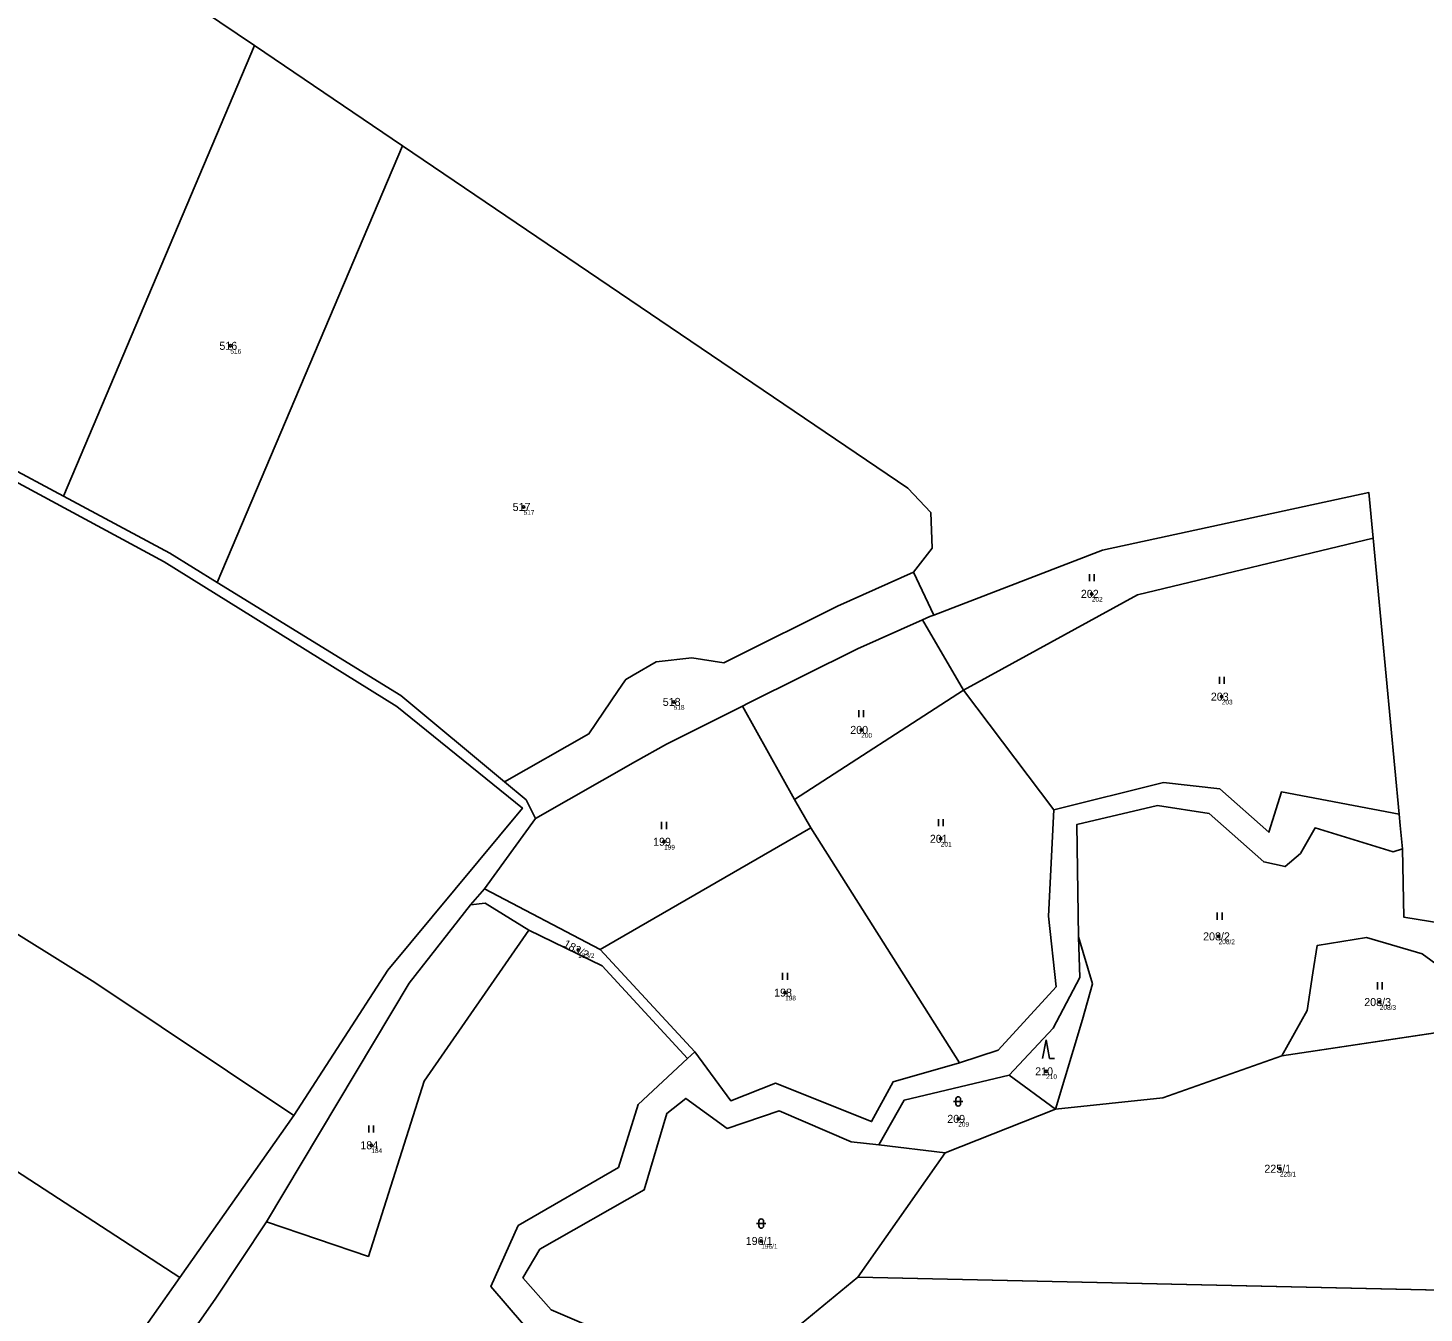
# Model space of a CAD drawing. Extents: x -700238 to -698499, y -1070626 to -1068006.
# Drawn here: x -699496.9 to -699200.2, y -1068765.8 to -1068492.8 of the extents above; entities that cross this region are included whole.
import ezdxf

# ---------------------------------------------------------------- set-up
doc = ezdxf.new("R2010")
doc.units = 0
for name, color, linetype in [('Definiční body', 7, 'Continuous'), ('Hranice parcel', 7, 'Continuous'), ('Parcelní čísla', 7, 'Continuous'), ('Polygon ku', 7, 'Continuous'), ('Polygon parcely', 7, 'Continuous'), ('Značky kultur', 7, 'Continuous')]:
    doc.layers.add(name, color=color, linetype=linetype)

msp = doc.modelspace()

# ---------------------------------------------------------------- linework, layer by layer
at = {"layer": 'Definiční body'}
for centre in [(-699453.85, -1068560.32994), (-699391.54, -1068594.54994), (-699270.81, -1068613.00994), (-699359.65, -1068635.95994), (-699243.2, -1068634.84994), (-699319.81, -1068641.90994), (-699361.7, -1068665.66994), (-699302.9, -1068665.03994), (-699243.87, -1068685.76994), (-699379.94, -1068688.68994), (-699335.99, -1068697.70994), (-699209.63, -1068699.71994), (-699280.52, -1068714.42994), (-699299.2, -1068724.52994), (-699423.9, -1068730.13994), (-699230.86, -1068735.11994), (-699341.05, -1068750.45994)]:
    msp.add_circle(centre, 0.25, dxfattribs=at)
at = {"layer": 'Hranice parcel'}
for p, q in [((-699459.74, -1068489.07), (-699448.71, -1068496.54)), ((-699489.31, -1068592.29), (-699448.71, -1068496.54)), ((-699448.71, -1068496.54), (-699417.3, -1068517.82)), ((-699456.64, -1068610.59), (-699417.3, -1068517.82)), ((-699211.93, -1068591.51), (-699211.02, -1068601.19)), ((-699211.02, -1068601.19), (-699205.5, -1068659.82)), ((-699308.68, -1068608.43), (-699304.4, -1068617.51)), ((-699305.24, -1068617.83), (-699306.78, -1068618.51)), ((-699304.4, -1068617.51), (-699305.24, -1068617.83)), ((-699306.78, -1068618.51), (-699320.61, -1068624.67)), ((-699298.09, -1068633.47), (-699306.78, -1068618.51)), ((-699334.01, -1068656.7), (-699298.09, -1068633.47)), ((-699298.09, -1068633.47), (-699278.9, -1068658.92)), ((-699345.02, -1068636.87), (-699334.01, -1068656.7)), ((-699330.48, -1068662.71), (-699334.01, -1068656.7)), ((-699205.5, -1068659.82), (-699205.28, -1068662.2)), ((-699399.84, -1068675.68), (-699389.04, -1068660.7)), ((-699330.48, -1068662.71), (-699375.27, -1068688.59)), ((-699298.89, -1068712.63), (-699330.48, -1068662.71)), ((-699205.28, -1068662.2), (-699204.82, -1068667.14)), ((-699402.82, -1068679.09), (-699399.84, -1068675.68)), ((-699375.27, -1068688.59), (-699399.84, -1068675.68)), ((-699355.18, -1068710.3), (-699375.27, -1068688.59)), ((-699176.6, -1068703.08), (-699230.46, -1068711.14)), ((-699355.18, -1068710.3), (-699356.75, -1068711.69)), ((-699278.5, -1068722.49), (-699288.39, -1068715.22)), ((-699440.37, -1068723.79), (-699464.55, -1068758.22)), ((-699302, -1068731.73), (-699278.5, -1068722.49)), ((-699302, -1068731.73), (-699316.06, -1068730.07)), ((-699320.54, -1068758.12), (-699302, -1068731.73)), ((-699320.54, -1068758.12), (-699164.78, -1068761.6))]:
    msp.add_line(p, q, dxfattribs=at)
for points in [[(-699417.3, -1068517.82), (-699309.92, -1068590.54), (-699305.03, -1068595.73), (-699304.73, -1068603.32), (-699308.68, -1068608.43)], [(-699489.31, -1068592.29), (-699514.72, -1068578.68), (-699545.8, -1068564.77), (-699583.54, -1068551.89)], [(-699584.32, -1068553.61), (-699551.31, -1068565.08), (-699541.03, -1068568.61), (-699514.77, -1068580.92), (-699467.93, -1068606.23), (-699418.44, -1068636.97), (-699391.79, -1068658.5), (-699420.37, -1068692.98), (-699440.37, -1068723.79)], [(-699211.93, -1068591.51), (-699268.51, -1068603.73), (-699304.4, -1068617.51)], [(-699456.64, -1068610.59), (-699466.71, -1068604.39), (-699489.31, -1068592.29)], [(-699211.02, -1068601.19), (-699261.08, -1068613.24), (-699298.09, -1068633.47)], [(-699440.37, -1068723.79), (-699482.65, -1068695.57), (-699529.3, -1068666.47), (-699581.06, -1068637.52), (-699612.14, -1068624.01), (-699666.08, -1068607.69)], [(-699395.63, -1068652.94), (-699377.65, -1068642.77), (-699371.43, -1068633.55), (-699370.04, -1068631.49), (-699369.83, -1068631.17), (-699368.26, -1068630.27), (-699363.39, -1068627.48), (-699355.83, -1068626.57), (-699349.02, -1068627.65), (-699347.33, -1068626.81), (-699324.87, -1068615.62), (-699308.68, -1068608.43)], [(-699395.63, -1068652.94), (-699417.63, -1068634.59), (-699456.64, -1068610.59)], [(-699320.61, -1068624.67), (-699343.8, -1068636.26), (-699345.02, -1068636.87)], [(-699345.02, -1068636.87), (-699361.16, -1068644.93), (-699367.73, -1068648.65), (-699389.04, -1068660.7)], [(-699464.55, -1068758.22), (-699502.54, -1068733.53), (-699525.94, -1068718.9), (-699568.74, -1068696.16), (-699607.46, -1068678.07), (-699629.84, -1068668.69), (-699681, -1068651.1)], [(-699389.04, -1068660.7), (-699391.02, -1068656.78), (-699395.63, -1068652.94)], [(-699278.9, -1068658.92), (-699255.58, -1068653.1), (-699243.64, -1068654.46), (-699233.19, -1068663.64), (-699230.52, -1068655.1), (-699205.5, -1068659.82)], [(-699278.9, -1068658.92), (-699279.98, -1068681.45), (-699278.42, -1068696.51), (-699290.72, -1068709.94), (-699298.89, -1068712.63)], [(-699204.82, -1068667.14), (-699206.78, -1068667.79), (-699223.37, -1068662.74), (-699226.5, -1068668.13), (-699229.76, -1068670.94), (-699234.28, -1068669.94), (-699245.88, -1068659.68), (-699256.83, -1068657.96), (-699273.96, -1068661.97), (-699273.66, -1068685.84)], [(-699204.82, -1068667.14), (-699204.5, -1068681.69), (-699164.43, -1068688.22)], [(-699446.16, -1068746.43), (-699415.83, -1068695.7), (-699402.82, -1068679.09)], [(-699402.82, -1068679.09), (-699399.72, -1068678.73), (-699390.45, -1068684.47)], [(-699390.45, -1068684.47), (-699412.7, -1068716.51), (-699424.51, -1068753.75), (-699446.16, -1068746.43)], [(-699356.75, -1068711.69), (-699374.88, -1068691.99), (-699390.45, -1068684.47)], [(-699273.66, -1068685.84), (-699273.35, -1068694.51), (-699279.04, -1068705.27), (-699288.39, -1068715.22)], [(-699273.66, -1068685.84), (-699270.66, -1068695.84), (-699272.81, -1068703.41), (-699278.5, -1068722.49)], [(-699223.88, -1068693.51), (-699222.92, -1068687.7), (-699212.44, -1068685.98), (-699200.59, -1068689.47), (-699186.19, -1068700.02), (-699176.6, -1068703.08)], [(-699230.46, -1068711.14), (-699225.05, -1068701.48), (-699223.88, -1068693.51)], [(-699298.89, -1068712.63), (-699313, -1068716.65), (-699317.62, -1068725.09), (-699338.04, -1068716.98), (-699347.54, -1068720.69), (-699355.18, -1068710.3)], [(-699356.75, -1068711.69), (-699367.23, -1068721.51), (-699371.39, -1068734.85), (-699392.66, -1068747.2), (-699398.53, -1068760.17), (-699391.56, -1068768.24), (-699373.96, -1068777.54), (-699357.08, -1068780.11), (-699360.38, -1068789.9)], [(-699278.5, -1068722.49), (-699255.75, -1068720.08), (-699230.46, -1068711.14)], [(-699288.39, -1068715.22), (-699310.66, -1068720.55), (-699316.06, -1068730.07)], [(-699316.06, -1068730.07), (-699321.93, -1068729.44), (-699337.26, -1068722.8), (-699348.26, -1068726.55), (-699357.08, -1068720.19), (-699361.09, -1068723.38), (-699365.93, -1068739.63), (-699388.09, -1068752.22), (-699391.67, -1068758.31), (-699385.67, -1068765.06), (-699371.18, -1068771.31), (-699347.69, -1068776.03), (-699353.13, -1068788.73), (-699359.83, -1068799.14)], [(-699467.03, -1068777.07), (-699457.09, -1068762.8), (-699446.16, -1068746.43)], [(-699464.55, -1068758.22), (-699476.32, -1068774.9), (-699498.94, -1068792.74)], [(-699346.21, -1068814.3), (-699343.01, -1068797.58), (-699332.59, -1068768.07), (-699320.54, -1068758.12)]]:
    msp.add_lwpolyline(points, dxfattribs=at)
at = {"layer": 'Polygon ku'}
msp.add_lwpolyline([(-699164.43, -1068688.22), (-699204.5, -1068681.69), (-699204.82, -1068667.14), (-699205.28, -1068662.2), (-699205.5, -1068659.82), (-699211.02, -1068601.19), (-699211.93, -1068591.51), (-699268.51, -1068603.73), (-699304.4, -1068617.51), (-699308.68, -1068608.43), (-699304.73, -1068603.32), (-699305.03, -1068595.73), (-699309.92, -1068590.54), (-699417.3, -1068517.82), (-699448.71, -1068496.54), (-699459.74, -1068489.07)], dxfattribs=at)
at = {"layer": 'Polygon parcely'}
for points in [[(-699459.74, -1068489.07), (-699534.75, -1068438.26), (-699538.81, -1068447.71), (-699583.54, -1068551.89), (-699545.8, -1068564.77), (-699514.72, -1068578.68), (-699489.31, -1068592.29), (-699448.71, -1068496.54)], [(-699456.64, -1068610.59), (-699417.3, -1068517.82), (-699448.71, -1068496.54), (-699489.31, -1068592.29), (-699466.71, -1068604.39)], [(-699309.92, -1068590.54), (-699417.3, -1068517.82), (-699456.64, -1068610.59), (-699417.63, -1068634.59), (-699395.63, -1068652.94), (-699377.65, -1068642.77), (-699371.43, -1068633.55), (-699370.04, -1068631.49), (-699369.83, -1068631.17), (-699368.26, -1068630.27), (-699363.39, -1068627.48), (-699355.83, -1068626.57), (-699349.02, -1068627.65), (-699347.33, -1068626.81), (-699324.87, -1068615.62), (-699308.68, -1068608.43), (-699304.73, -1068603.32), (-699305.03, -1068595.73)], [(-699684.13, -1068602.07), (-699666.08, -1068607.69), (-699612.14, -1068624.01), (-699581.06, -1068637.52), (-699529.3, -1068666.47), (-699482.65, -1068695.57), (-699440.37, -1068723.79), (-699420.37, -1068692.98), (-699391.79, -1068658.5), (-699418.44, -1068636.97), (-699467.93, -1068606.23), (-699514.77, -1068580.92), (-699541.03, -1068568.61), (-699551.31, -1068565.08), (-699584.32, -1068553.61), (-699655.01, -1068532.14), (-699671.14, -1068527.69), (-699680.08, -1068567.69)], [(-699268.51, -1068603.73), (-699304.4, -1068617.51), (-699305.24, -1068617.83), (-699306.78, -1068618.51), (-699298.09, -1068633.47), (-699261.08, -1068613.24), (-699211.02, -1068601.19), (-699211.93, -1068591.51)], [(-699298.09, -1068633.47), (-699278.9, -1068658.92), (-699255.58, -1068653.1), (-699243.64, -1068654.46), (-699233.19, -1068663.64), (-699230.52, -1068655.1), (-699205.5, -1068659.82), (-699211.02, -1068601.19), (-699261.08, -1068613.24)], [(-699673.34, -1068630.67), (-699681, -1068651.1), (-699629.84, -1068668.69), (-699607.46, -1068678.07), (-699568.74, -1068696.16), (-699525.94, -1068718.9), (-699502.54, -1068733.53), (-699464.55, -1068758.22), (-699440.37, -1068723.79), (-699482.65, -1068695.57), (-699529.3, -1068666.47), (-699581.06, -1068637.52), (-699612.14, -1068624.01), (-699666.08, -1068607.69)], [(-699320.61, -1068624.67), (-699306.78, -1068618.51), (-699305.24, -1068617.83), (-699304.4, -1068617.51), (-699308.68, -1068608.43), (-699324.87, -1068615.62), (-699347.33, -1068626.81), (-699349.02, -1068627.65), (-699355.83, -1068626.57), (-699363.39, -1068627.48), (-699368.26, -1068630.27), (-699369.83, -1068631.17), (-699370.04, -1068631.49), (-699371.43, -1068633.55), (-699377.65, -1068642.77), (-699395.63, -1068652.94), (-699391.02, -1068656.78), (-699389.04, -1068660.7), (-699367.73, -1068648.65), (-699361.16, -1068644.93), (-699345.02, -1068636.87), (-699343.8, -1068636.26)], [(-699345.02, -1068636.87), (-699334.01, -1068656.7), (-699298.09, -1068633.47), (-699306.78, -1068618.51), (-699320.61, -1068624.67), (-699343.8, -1068636.26)], [(-699334.01, -1068656.7), (-699330.48, -1068662.71), (-699298.89, -1068712.63), (-699290.72, -1068709.94), (-699278.42, -1068696.51), (-699279.98, -1068681.45), (-699278.9, -1068658.92), (-699298.09, -1068633.47)], [(-699334.01, -1068656.7), (-699345.02, -1068636.87), (-699361.16, -1068644.93), (-699367.73, -1068648.65), (-699389.04, -1068660.7), (-699399.84, -1068675.68), (-699375.27, -1068688.59), (-699330.48, -1068662.71)], [(-699682.47, -1068655.58), (-699692.25, -1068684.81), (-699695.12, -1068702.49), (-699640.97, -1068718.81), (-699602.77, -1068734.4), (-699577.98, -1068745.62), (-699550.82, -1068759.4), (-699524.87, -1068774.77), (-699498.94, -1068792.74), (-699476.32, -1068774.9), (-699464.55, -1068758.22), (-699502.54, -1068733.53), (-699525.94, -1068718.9), (-699568.74, -1068696.16), (-699607.46, -1068678.07), (-699629.84, -1068668.69), (-699681, -1068651.1)], [(-699330.48, -1068662.71), (-699375.27, -1068688.59), (-699355.18, -1068710.3), (-699347.54, -1068720.69), (-699338.04, -1068716.98), (-699317.62, -1068725.09), (-699313, -1068716.65), (-699298.89, -1068712.63)], [(-699375.27, -1068688.59), (-699399.84, -1068675.68), (-699402.82, -1068679.09), (-699399.72, -1068678.73), (-699390.45, -1068684.47), (-699374.88, -1068691.99), (-699356.75, -1068711.69), (-699355.18, -1068710.3)], [(-699446.16, -1068746.43), (-699424.51, -1068753.75), (-699412.7, -1068716.51), (-699390.45, -1068684.47), (-699399.72, -1068678.73), (-699402.82, -1068679.09), (-699415.83, -1068695.7)], [(-699374.88, -1068691.99), (-699390.45, -1068684.47), (-699412.7, -1068716.51), (-699424.51, -1068753.75), (-699446.16, -1068746.43), (-699457.09, -1068762.8), (-699467.03, -1068777.07), (-699444.09, -1068780.91), (-699429.91, -1068808.67), (-699360.38, -1068789.9), (-699357.08, -1068780.11), (-699373.96, -1068777.54), (-699391.56, -1068768.24), (-699398.53, -1068760.17), (-699392.66, -1068747.2), (-699371.39, -1068734.85), (-699367.23, -1068721.51), (-699356.75, -1068711.69)], [(-699273.66, -1068685.84), (-699273.35, -1068694.51), (-699279.04, -1068705.27), (-699288.39, -1068715.22), (-699278.5, -1068722.49), (-699272.81, -1068703.41), (-699270.66, -1068695.84)], [(-699230.46, -1068711.14), (-699176.6, -1068703.08), (-699186.19, -1068700.02), (-699200.59, -1068689.47), (-699212.44, -1068685.98), (-699222.92, -1068687.7), (-699223.88, -1068693.51), (-699225.05, -1068701.48)], [(-699320.54, -1068758.12), (-699164.78, -1068761.6), (-699162.58, -1068695.94), (-699176.6, -1068703.08), (-699230.46, -1068711.14), (-699255.75, -1068720.08), (-699278.5, -1068722.49), (-699302, -1068731.73)], [(-699288.39, -1068715.22), (-699310.66, -1068720.55), (-699316.06, -1068730.07), (-699302, -1068731.73), (-699278.5, -1068722.49)], [(-699357.08, -1068720.19), (-699361.09, -1068723.38), (-699365.93, -1068739.63), (-699388.09, -1068752.22), (-699391.67, -1068758.31), (-699385.67, -1068765.06), (-699371.18, -1068771.31), (-699347.69, -1068776.03), (-699353.13, -1068788.73), (-699359.83, -1068799.14), (-699359.15, -1068805.09), (-699346.21, -1068814.3), (-699343.01, -1068797.58), (-699332.59, -1068768.07), (-699320.54, -1068758.12), (-699302, -1068731.73), (-699316.06, -1068730.07), (-699321.93, -1068729.44), (-699337.26, -1068722.8), (-699348.26, -1068726.55)], [(-699346.21, -1068814.3), (-699244.79, -1068817.34), (-699112.1, -1068824.87), (-699095.55, -1068762.45), (-699164.78, -1068761.6), (-699320.54, -1068758.12), (-699332.59, -1068768.07), (-699343.01, -1068797.58)]]:
    msp.add_lwpolyline(points, close=True, dxfattribs=at)
for points in [[(-699536.5, -1068849.9), (-699489.21, -1068798.95), (-699469.58, -1068780.23), (-699467.03, -1068777.07), (-699457.09, -1068762.8), (-699446.16, -1068746.43), (-699415.83, -1068695.7), (-699402.82, -1068679.09), (-699399.84, -1068675.68), (-699389.04, -1068660.7), (-699391.02, -1068656.78), (-699395.63, -1068652.94), (-699417.63, -1068634.59), (-699456.64, -1068610.59), (-699466.71, -1068604.39), (-699489.31, -1068592.29), (-699514.72, -1068578.68)], [(-699514.77, -1068580.92), (-699467.93, -1068606.23), (-699418.44, -1068636.97), (-699391.79, -1068658.5), (-699420.37, -1068692.98), (-699440.37, -1068723.79), (-699464.55, -1068758.22), (-699476.32, -1068774.9), (-699498.94, -1068792.74)], [(-699371.18, -1068771.31), (-699385.67, -1068765.06), (-699391.67, -1068758.31), (-699388.09, -1068752.22), (-699365.93, -1068739.63), (-699361.09, -1068723.38), (-699357.08, -1068720.19), (-699348.26, -1068726.55), (-699337.26, -1068722.8), (-699321.93, -1068729.44), (-699316.06, -1068730.07), (-699310.66, -1068720.55), (-699288.39, -1068715.22), (-699279.04, -1068705.27), (-699273.35, -1068694.51), (-699273.66, -1068685.84), (-699273.96, -1068661.97), (-699256.83, -1068657.96), (-699245.88, -1068659.68), (-699234.28, -1068669.94), (-699229.76, -1068670.94), (-699226.5, -1068668.13), (-699223.37, -1068662.74), (-699206.78, -1068667.79), (-699204.82, -1068667.14), (-699205.28, -1068662.2), (-699205.5, -1068659.82), (-699230.52, -1068655.1), (-699233.19, -1068663.64), (-699243.64, -1068654.46), (-699255.58, -1068653.1), (-699278.9, -1068658.92), (-699279.98, -1068681.45), (-699278.42, -1068696.51), (-699290.72, -1068709.94), (-699298.89, -1068712.63), (-699313, -1068716.65), (-699317.62, -1068725.09), (-699338.04, -1068716.98), (-699347.54, -1068720.69), (-699355.18, -1068710.3), (-699356.75, -1068711.69), (-699367.23, -1068721.51), (-699371.39, -1068734.85), (-699392.66, -1068747.2), (-699398.53, -1068760.17), (-699391.56, -1068768.24)], [(-699164.43, -1068688.22), (-699204.5, -1068681.69), (-699204.82, -1068667.14), (-699206.78, -1068667.79), (-699223.37, -1068662.74), (-699226.5, -1068668.13), (-699229.76, -1068670.94), (-699234.28, -1068669.94), (-699245.88, -1068659.68), (-699256.83, -1068657.96), (-699273.96, -1068661.97), (-699273.66, -1068685.84), (-699270.66, -1068695.84), (-699272.81, -1068703.41), (-699278.5, -1068722.49), (-699255.75, -1068720.08), (-699230.46, -1068711.14), (-699225.05, -1068701.48), (-699223.88, -1068693.51), (-699222.92, -1068687.7), (-699212.44, -1068685.98), (-699200.59, -1068689.47), (-699186.19, -1068700.02)]]:
    msp.add_lwpolyline(points, dxfattribs=at)
at = {"layer": 'Značky kultur'}
for p, q in [((-699271.321, -1068610.31), (-699271.321, -1068608.81)), ((-699270.32, -1068610.31), (-699270.32, -1068608.81)), ((-699243.711, -1068632.15), (-699243.711, -1068630.65)), ((-699242.71, -1068632.15), (-699242.71, -1068630.65)), ((-699320.321, -1068639.21), (-699320.321, -1068637.71)), ((-699319.32, -1068639.21), (-699319.32, -1068637.71)), ((-699362.211, -1068662.97), (-699362.211, -1068661.47)), ((-699361.21, -1068662.97), (-699361.21, -1068661.47)), ((-699303.411, -1068662.34), (-699303.411, -1068660.84)), ((-699302.41, -1068662.34), (-699302.41, -1068660.84)), ((-699244.151, -1068682.23), (-699244.151, -1068680.73)), ((-699243.15, -1068682.23), (-699243.15, -1068680.73)), ((-699336.501, -1068695.01), (-699336.501, -1068693.51)), ((-699335.5, -1068695.01), (-699335.5, -1068693.51)), ((-699210.141, -1068697.02), (-699210.141, -1068695.52)), ((-699209.14, -1068697.02), (-699209.14, -1068695.52)), ((-699280.52, -1068707.73), (-699281.27, -1068711.73)), ((-699279.77, -1068711.73), (-699280.52, -1068707.73)), ((-699279.77, -1068711.73), (-699278.774, -1068711.73)), ((-699300.201, -1068720.831), (-699298.199, -1068720.831)), ((-699299.701, -1068720.331), (-699299.701, -1068721.332)), ((-699298.699, -1068721.332), (-699298.699, -1068720.331)), ((-699424.411, -1068727.44), (-699424.411, -1068725.94)), ((-699423.41, -1068727.44), (-699423.41, -1068725.94)), ((-699342.051, -1068746.761), (-699340.049, -1068746.761)), ((-699341.551, -1068746.261), (-699341.551, -1068747.262)), ((-699340.549, -1068747.262), (-699340.549, -1068746.261))]:
    msp.add_line(p, q, dxfattribs=at)
for centre, start, end in [((-699299.2, -1068720.3309), 0, 180), ((-699299.2, -1068721.3309), 180, 359.9878861), ((-699341.05, -1068746.2609), 0, 180), ((-699341.05, -1068747.2609), 180, 359.9878861)]:
    msp.add_arc(centre, 0.5, start, end, dxfattribs=at)

# ---------------------------------------------------------------- texts
at = {"layer": 'Definiční body'}
for s, p in [('516', (-699453.85, -1068561.986)), ('517', (-699391.54, -1068596.206)), ('202', (-699270.81, -1068614.666)), ('203', (-699243.2, -1068636.506)), ('518', (-699359.65, -1068637.616)), ('200', (-699319.81, -1068643.566)), ('201', (-699302.9, -1068666.696)), ('199', (-699361.7, -1068667.326)), ('208/2', (-699243.87, -1068687.426)), ('183/2', (-699379.94, -1068690.346)), ('198', (-699335.99, -1068699.366)), ('208/3', (-699209.63, -1068701.376)), ('210', (-699280.52, -1068716.086)), ('209', (-699299.2, -1068726.186)), ('184', (-699423.9, -1068731.796)), ('225/1', (-699230.86, -1068736.776)), ('196/1', (-699341.05, -1068752.116))]:
    msp.add_text(s, height=0.999996, dxfattribs=at).set_placement(p)
at = {"layer": 'Parcelní čísla'}
for s, p in [('516', (-699456.175, -1068561.18)), ('517', (-699393.865, -1068595.4)), ('202', (-699273.135, -1068613.86)), ('518', (-699361.975, -1068636.81)), ('203', (-699245.525, -1068635.7)), ('200', (-699322.135, -1068642.759)), ('199', (-699364.025, -1068666.519)), ('201', (-699305.225, -1068665.89)), ('208/2', (-699247.168, -1068686.62)), ('198', (-699338.315, -1068698.56)), ('208/3', (-699212.928, -1068700.57)), ('210', (-699282.845, -1068715.279)), ('209', (-699301.525, -1068725.38)), ('184', (-699426.225, -1068730.989)), ('225/1', (-699234.158, -1068735.97)), ('196/1', (-699344.348, -1068751.31))]:
    msp.add_text(s, height=1.699998, dxfattribs=at).set_placement(p)
msp.add_text('183/2', height=1.699998, rotation=331, dxfattribs=at).set_placement((-699383.237, -1068687.834))

doc.saveas('drawing.dxf')
